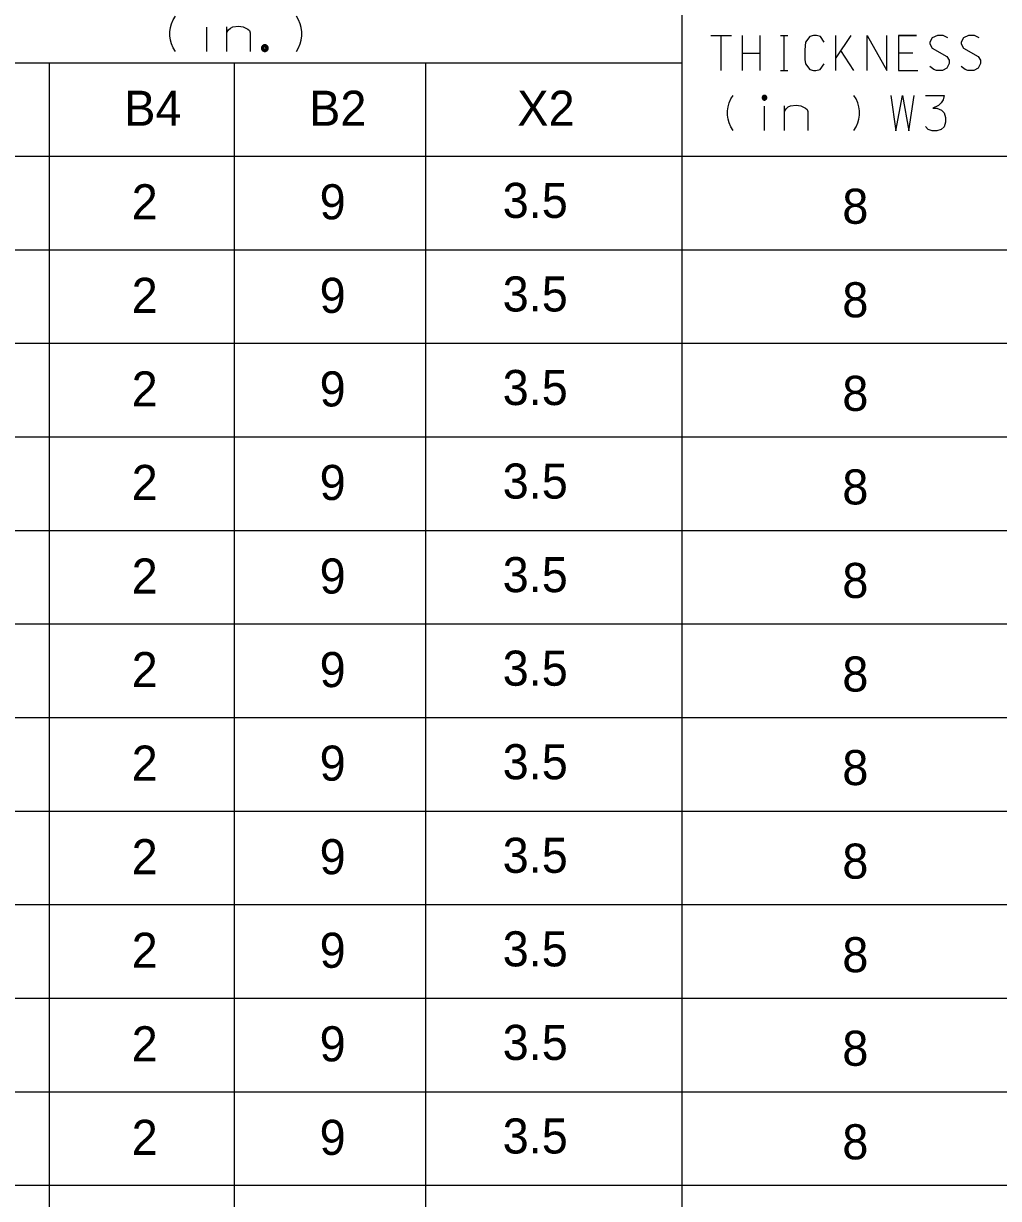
# Model space of a CAD drawing. Extents: x 635698 to 639877, y 296617 to 300175.
# Drawn here: x 639114.2 to 639197.6, y 298708.2 to 298808.7 of the extents above; entities that cross this region are included whole.
import ezdxf

# ---------------------------------------------------------------- set-up
doc = ezdxf.new("R2010")
doc.units = 0
for name, color, linetype in [('1', 7, 'Continuous'), ('2', 7, 'Continuous'), ('3', 7, 'Continuous')]:
    doc.layers.add(name, color=color, linetype=linetype)

msp = doc.modelspace()

# ---------------------------------------------------------------- linework, layer by layer
at = {"layer": '1'}
for points in [[(639173.01, 298807.65), (639174.79, 298807.65)], [(639173.9, 298804.65), (639173.9, 298807.65)], [(639173.9, 298804.65), (639173.9, 298807.65)], [(639175.68, 298807.65), (639175.68, 298804.65)], [(639177.21, 298807.65), (639177.21, 298804.65)], [(639178.96, 298807.65), (639179.59, 298807.65)], [(639179.28, 298804.65), (639179.28, 298807.65)], [(639182.72, 298807.06), (639182.38, 298807.55), (639182.04, 298807.65), (639181.8, 298807.65), (639181.49, 298807.55), (639181.12, 298807.06), (639181.04, 298806.4), (639181.04, 298806.04), (639181.04, 298805.81), (639181.06, 298805.59), (639181.12, 298805.22), (639181.49, 298804.74), (639181.8, 298804.65), (639182, 298804.65), (639182.36, 298804.74), (639182.72, 298805.22)], [(639183.72, 298804.65), (639183.72, 298807.65)], [(639184.99, 298807.65), (639183.72, 298805.74)], [(639186.4, 298804.65), (639186.4, 298807.65), (639188.07, 298804.65), (639188.07, 298807.65)], [(639190.62, 298807.65), (639189.07, 298807.65), (639189.07, 298804.65), (639190.73, 298804.65)], [(639189.07, 298807.65), (639190.62, 298807.65)], [(639193.3, 298807.44), (639192.88, 298807.65), (639192.39, 298807.65), (639191.94, 298807.44), (639191.75, 298807.06), (639191.75, 298806.92), (639191.96, 298806.56), (639193.2, 298805.85), (639193.41, 298805.52), (639193.39, 298805.24), (639193.2, 298804.86), (639192.83, 298804.65), (639192.32, 298804.65), (639192.09, 298804.74), (639191.75, 298805)], [(639195.98, 298807.44), (639195.56, 298807.65), (639195.07, 298807.65), (639194.62, 298807.44), (639194.43, 298807.06), (639194.43, 298806.92), (639194.64, 298806.56), (639195.87, 298805.85), (639196.09, 298805.52), (639196.07, 298805.24), (639195.87, 298804.86), (639195.51, 298804.65), (639195, 298804.65), (639194.77, 298804.74), (639194.43, 298805)], [(639185.25, 298804.65), (639184.14, 298806.35)], [(639175.68, 298806.14), (639177.21, 298806.14)], [(639189.07, 298806.16), (639190.29, 298806.16)], [(639189.07, 298806.16), (639190.29, 298806.16)], [(639178.96, 298804.65), (639179.59, 298804.65)]]:
    msp.add_lwpolyline(points, dxfattribs=at)
at = {"layer": '2'}
for p, q in [((639170.53, 298814.79), (639170.53, 298581.29)), ((639100.52, 298805.29), (639170.53, 298805.29)), ((639116.4, 298805.29), (639116.4, 298581.29)), ((639132.22, 298805.29), (639132.22, 298581.29)), ((639148.59, 298805.29), (639148.59, 298581.29)), ((639405.11, 298797.29), (638853.27, 298797.29)), ((639405.11, 298789.29), (638853.27, 298789.29)), ((639405.11, 298781.29), (638853.27, 298781.29)), ((639405.11, 298773.29), (638853.27, 298773.29)), ((639405.11, 298765.29), (638853.27, 298765.29)), ((639405.11, 298757.29), (638853.27, 298757.29)), ((639405.11, 298749.29), (638853.27, 298749.29)), ((639405.11, 298741.29), (638853.27, 298741.29)), ((639405.11, 298733.29), (638853.27, 298733.29)), ((639405.11, 298725.29), (638853.27, 298725.29)), ((639405.11, 298725.29), (638853.27, 298725.29)), ((639405.11, 298717.29), (638853.27, 298717.29)), ((639405.11, 298709.29), (638853.27, 298709.29))]:
    msp.add_line(p, q, dxfattribs=at)
at = {"layer": '3'}
for points in [[(639127.21, 298806.28), (639127.02, 298806.58), (639126.87, 298806.92), (639126.78, 298807.25), (639126.73, 298807.6), (639126.73, 298807.95), (639126.78, 298808.31), (639126.87, 298808.64), (639127.02, 298808.97), (639127.21, 298809.28)], [(639129.89, 298806.28), (639129.89, 298808.36)], [(639131.59, 298807.91), (639131.75, 298808.12), (639131.92, 298808.28), (639132.13, 298808.38), (639132.61, 298808.45), (639133.01, 298808.38), (639133.41, 298808.19), (639133.53, 298808.07), (639133.6, 298807.88), (639133.6, 298806.28)], [(639131.59, 298806.28), (639131.59, 298808.38)], [(639137.55, 298806.28), (639137.74, 298806.58), (639137.88, 298806.92), (639137.97, 298807.25), (639138.02, 298807.6), (639138.02, 298807.95), (639137.97, 298808.31), (639137.88, 298808.64), (639137.74, 298808.97), (639137.55, 298809.28)], [(639135.14, 298806.56), (639135.14, 298806.59), (639135.13, 298806.62), (639135.13, 298806.65), (639135.11, 298806.68), (639135.1, 298806.7), (639135.08, 298806.73), (639135.07, 298806.75), (639135.04, 298806.77), (639135.02, 298806.79), (639135, 298806.81), (639134.97, 298806.82), (639134.94, 298806.83), (639134.91, 298806.84), (639134.88, 298806.85), (639134.85, 298806.85), (639134.82, 298806.85), (639134.79, 298806.84), (639134.77, 298806.83), (639134.74, 298806.82), (639134.71, 298806.81), (639134.69, 298806.79), (639134.66, 298806.77), (639134.64, 298806.75), (639134.62, 298806.73), (639134.61, 298806.7), (639134.59, 298806.68), (639134.58, 298806.65), (639134.58, 298806.62), (639134.57, 298806.59), (639134.57, 298806.56), (639134.57, 298806.53), (639134.58, 298806.5), (639134.58, 298806.47), (639134.59, 298806.45), (639134.61, 298806.42), (639134.62, 298806.39), (639134.64, 298806.37), (639134.66, 298806.35), (639134.69, 298806.33), (639134.71, 298806.32), (639134.74, 298806.3), (639134.77, 298806.29), (639134.79, 298806.28), (639134.82, 298806.28), (639134.85, 298806.28), (639134.88, 298806.28), (639134.91, 298806.28), (639134.94, 298806.29), (639134.97, 298806.3), (639135, 298806.32), (639135.02, 298806.33), (639135.04, 298806.35), (639135.07, 298806.37), (639135.08, 298806.39), (639135.1, 298806.42), (639135.11, 298806.45), (639135.13, 298806.47), (639135.13, 298806.5), (639135.14, 298806.53), (639135.14, 298806.56)], [(639135.08, 298806.56), (639135.08, 298806.59), (639135.07, 298806.61), (639135.07, 298806.63), (639135.06, 298806.65), (639135.05, 298806.67), (639135.04, 298806.69), (639135.02, 298806.71), (639135, 298806.73), (639134.99, 298806.74), (639134.97, 298806.76), (639134.95, 298806.77), (639134.92, 298806.78), (639134.9, 298806.78), (639134.88, 298806.79), (639134.85, 298806.79), (639134.83, 298806.79), (639134.81, 298806.78), (639134.78, 298806.78), (639134.76, 298806.77), (639134.74, 298806.76), (639134.72, 298806.74), (639134.7, 298806.73), (639134.69, 298806.71), (639134.67, 298806.69), (639134.66, 298806.67), (639134.65, 298806.65), (639134.64, 298806.63), (639134.63, 298806.61), (639134.63, 298806.59), (639134.63, 298806.56), (639134.63, 298806.54), (639134.63, 298806.52), (639134.64, 298806.49), (639134.65, 298806.47), (639134.66, 298806.45), (639134.67, 298806.43), (639134.69, 298806.41), (639134.7, 298806.39), (639134.72, 298806.38), (639134.74, 298806.37), (639134.76, 298806.36), (639134.78, 298806.35), (639134.81, 298806.34), (639134.83, 298806.34), (639134.85, 298806.34), (639134.88, 298806.34), (639134.9, 298806.34), (639134.92, 298806.35), (639134.95, 298806.36), (639134.97, 298806.37), (639134.99, 298806.38), (639135, 298806.39), (639135.02, 298806.41), (639135.04, 298806.43), (639135.05, 298806.45), (639135.06, 298806.47), (639135.07, 298806.49), (639135.07, 298806.52), (639135.08, 298806.54), (639135.08, 298806.56)], [(639135.02, 298806.56), (639135.02, 298806.58), (639135.02, 298806.6), (639135.01, 298806.61), (639135, 298806.63), (639135, 298806.64), (639134.99, 298806.66), (639134.98, 298806.67), (639134.96, 298806.68), (639134.95, 298806.7), (639134.94, 298806.7), (639134.92, 298806.71), (639134.9, 298806.72), (639134.89, 298806.72), (639134.87, 298806.73), (639134.85, 298806.73), (639134.84, 298806.73), (639134.82, 298806.72), (639134.8, 298806.72), (639134.79, 298806.71), (639134.77, 298806.7), (639134.76, 298806.7), (639134.74, 298806.68), (639134.73, 298806.67), (639134.72, 298806.66), (639134.71, 298806.64), (639134.7, 298806.63), (639134.7, 298806.61), (639134.69, 298806.6), (639134.69, 298806.58), (639134.69, 298806.56), (639134.69, 298806.54), (639134.69, 298806.53), (639134.7, 298806.51), (639134.7, 298806.49), (639134.71, 298806.48), (639134.72, 298806.46), (639134.73, 298806.45), (639134.74, 298806.44), (639134.76, 298806.43), (639134.77, 298806.42), (639134.79, 298806.41), (639134.8, 298806.4), (639134.82, 298806.4), (639134.84, 298806.4), (639134.85, 298806.4), (639134.87, 298806.4), (639134.89, 298806.4), (639134.9, 298806.4), (639134.92, 298806.41), (639134.94, 298806.42), (639134.95, 298806.43), (639134.96, 298806.44), (639134.98, 298806.45), (639134.99, 298806.46), (639135, 298806.48), (639135, 298806.49), (639135.01, 298806.51), (639135.02, 298806.53), (639135.02, 298806.54), (639135.02, 298806.56)], [(639134.96, 298806.56), (639134.96, 298806.57), (639134.96, 298806.58), (639134.95, 298806.59), (639134.95, 298806.6), (639134.94, 298806.61), (639134.94, 298806.62), (639134.93, 298806.63), (639134.92, 298806.64), (639134.92, 298806.65), (639134.91, 298806.65), (639134.9, 298806.66), (639134.89, 298806.66), (639134.88, 298806.66), (639134.87, 298806.67), (639134.85, 298806.67), (639134.84, 298806.67), (639134.83, 298806.66), (639134.82, 298806.66), (639134.81, 298806.66), (639134.8, 298806.65), (639134.79, 298806.65), (639134.78, 298806.64), (639134.78, 298806.63), (639134.77, 298806.62), (639134.76, 298806.61), (639134.76, 298806.6), (639134.75, 298806.59), (639134.75, 298806.58), (639134.75, 298806.57), (639134.75, 298806.56), (639134.75, 298806.55), (639134.75, 298806.54), (639134.75, 298806.53), (639134.76, 298806.52), (639134.76, 298806.51), (639134.77, 298806.5), (639134.78, 298806.49), (639134.78, 298806.48), (639134.79, 298806.48), (639134.8, 298806.47), (639134.81, 298806.47), (639134.82, 298806.46), (639134.83, 298806.46), (639134.84, 298806.46), (639134.85, 298806.46), (639134.87, 298806.46), (639134.88, 298806.46), (639134.89, 298806.46), (639134.9, 298806.47), (639134.91, 298806.47), (639134.92, 298806.48), (639134.92, 298806.48), (639134.93, 298806.49), (639134.94, 298806.5), (639134.94, 298806.51), (639134.95, 298806.52), (639134.95, 298806.53), (639134.96, 298806.54), (639134.96, 298806.55), (639134.96, 298806.56)], [(639174.92, 298799.52), (639174.73, 298799.83), (639174.59, 298800.16), (639174.5, 298800.49), (639174.45, 298800.84), (639174.45, 298801.2), (639174.5, 298801.55), (639174.59, 298801.88), (639174.73, 298802.21), (639174.92, 298802.52)], [(639177.8, 298802.32), (639177.8, 298802.34), (639177.79, 298802.36), (639177.79, 298802.38), (639177.78, 298802.4), (639177.77, 298802.42), (639177.76, 298802.44), (639177.75, 298802.45), (639177.73, 298802.47), (639177.72, 298802.48), (639177.7, 298802.49), (639177.68, 298802.5), (639177.66, 298802.51), (639177.64, 298802.51), (639177.62, 298802.52), (639177.6, 298802.52), (639177.58, 298802.52), (639177.56, 298802.51), (639177.54, 298802.51), (639177.52, 298802.5), (639177.5, 298802.49), (639177.48, 298802.48), (639177.47, 298802.47), (639177.45, 298802.45), (639177.44, 298802.44), (639177.43, 298802.42), (639177.42, 298802.4), (639177.41, 298802.38), (639177.41, 298802.36), (639177.4, 298802.34), (639177.4, 298802.32), (639177.4, 298802.3), (639177.41, 298802.28), (639177.41, 298802.26), (639177.42, 298802.24), (639177.43, 298802.22), (639177.44, 298802.2), (639177.45, 298802.19), (639177.47, 298802.17), (639177.48, 298802.16), (639177.5, 298802.15), (639177.52, 298802.14), (639177.54, 298802.13), (639177.56, 298802.13), (639177.58, 298802.12), (639177.6, 298802.12), (639177.62, 298802.12), (639177.64, 298802.13), (639177.66, 298802.13), (639177.68, 298802.14), (639177.7, 298802.15), (639177.72, 298802.16), (639177.73, 298802.17), (639177.75, 298802.19), (639177.76, 298802.2), (639177.77, 298802.22), (639177.78, 298802.24), (639177.79, 298802.26), (639177.79, 298802.28), (639177.8, 298802.3), (639177.8, 298802.32)], [(639177.74, 298802.32), (639177.74, 298802.34), (639177.74, 298802.35), (639177.73, 298802.36), (639177.73, 298802.38), (639177.72, 298802.39), (639177.71, 298802.4), (639177.7, 298802.41), (639177.69, 298802.42), (639177.68, 298802.43), (639177.67, 298802.44), (639177.66, 298802.45), (639177.64, 298802.45), (639177.63, 298802.46), (639177.62, 298802.46), (639177.6, 298802.46), (639177.59, 298802.46), (639177.57, 298802.46), (639177.56, 298802.45), (639177.54, 298802.45), (639177.53, 298802.44), (639177.52, 298802.43), (639177.51, 298802.42), (639177.5, 298802.41), (639177.49, 298802.4), (639177.48, 298802.39), (639177.47, 298802.38), (639177.47, 298802.36), (639177.47, 298802.35), (639177.46, 298802.34), (639177.46, 298802.32), (639177.46, 298802.31), (639177.47, 298802.29), (639177.47, 298802.28), (639177.47, 298802.26), (639177.48, 298802.25), (639177.49, 298802.24), (639177.5, 298802.23), (639177.51, 298802.22), (639177.52, 298802.21), (639177.53, 298802.2), (639177.54, 298802.2), (639177.56, 298802.19), (639177.57, 298802.19), (639177.59, 298802.18), (639177.6, 298802.18), (639177.62, 298802.18), (639177.63, 298802.19), (639177.64, 298802.19), (639177.66, 298802.2), (639177.67, 298802.2), (639177.68, 298802.21), (639177.69, 298802.22), (639177.7, 298802.23), (639177.71, 298802.24), (639177.72, 298802.25), (639177.73, 298802.26), (639177.73, 298802.28), (639177.74, 298802.29), (639177.74, 298802.31), (639177.74, 298802.32)], [(639177.68, 298802.32), (639177.68, 298802.33), (639177.68, 298802.34), (639177.67, 298802.35), (639177.67, 298802.35), (639177.67, 298802.36), (639177.66, 298802.37), (639177.66, 298802.37), (639177.65, 298802.38), (639177.65, 298802.38), (639177.64, 298802.39), (639177.63, 298802.39), (639177.63, 298802.39), (639177.62, 298802.4), (639177.61, 298802.4), (639177.6, 298802.4), (639177.59, 298802.4), (639177.58, 298802.4), (639177.58, 298802.39), (639177.57, 298802.39), (639177.56, 298802.39), (639177.56, 298802.38), (639177.55, 298802.38), (639177.54, 298802.37), (639177.54, 298802.37), (639177.53, 298802.36), (639177.53, 298802.35), (639177.53, 298802.35), (639177.52, 298802.34), (639177.52, 298802.33), (639177.52, 298802.32), (639177.52, 298802.31), (639177.52, 298802.3), (639177.53, 298802.3), (639177.53, 298802.29), (639177.53, 298802.28), (639177.54, 298802.28), (639177.54, 298802.27), (639177.55, 298802.26), (639177.56, 298802.26), (639177.56, 298802.25), (639177.57, 298802.25), (639177.58, 298802.25), (639177.58, 298802.24), (639177.59, 298802.24), (639177.6, 298802.24), (639177.61, 298802.24), (639177.62, 298802.24), (639177.63, 298802.25), (639177.63, 298802.25), (639177.64, 298802.25), (639177.65, 298802.26), (639177.65, 298802.26), (639177.66, 298802.27), (639177.66, 298802.28), (639177.67, 298802.28), (639177.67, 298802.29), (639177.67, 298802.3), (639177.68, 298802.3), (639177.68, 298802.31), (639177.68, 298802.32)], [(639177.62, 298802.32), (639177.62, 298802.32), (639177.62, 298802.32), (639177.62, 298802.33), (639177.62, 298802.33), (639177.62, 298802.33), (639177.62, 298802.33), (639177.61, 298802.33), (639177.61, 298802.33), (639177.61, 298802.34), (639177.61, 298802.34), (639177.61, 298802.34), (639177.61, 298802.34), (639177.6, 298802.34), (639177.6, 298802.34), (639177.6, 298802.34), (639177.6, 298802.34), (639177.6, 298802.34), (639177.6, 298802.34), (639177.59, 298802.34), (639177.59, 298802.34), (639177.59, 298802.34), (639177.59, 298802.33), (639177.59, 298802.33), (639177.59, 298802.33), (639177.59, 298802.33), (639177.58, 298802.33), (639177.58, 298802.33), (639177.58, 298802.32), (639177.58, 298802.32), (639177.58, 298802.32), (639177.58, 298802.32), (639177.58, 298802.32), (639177.58, 298802.32), (639177.58, 298802.31), (639177.59, 298802.31), (639177.59, 298802.31), (639177.59, 298802.31), (639177.59, 298802.31), (639177.59, 298802.31), (639177.59, 298802.31), (639177.59, 298802.3), (639177.6, 298802.3), (639177.6, 298802.3), (639177.6, 298802.3), (639177.6, 298802.3), (639177.6, 298802.3), (639177.6, 298802.3), (639177.61, 298802.3), (639177.61, 298802.3), (639177.61, 298802.31), (639177.61, 298802.31), (639177.61, 298802.31), (639177.61, 298802.31), (639177.62, 298802.31), (639177.62, 298802.31), (639177.62, 298802.31), (639177.62, 298802.32), (639177.62, 298802.32), (639177.62, 298802.32), (639177.62, 298802.32)], [(639185.25, 298799.52), (639185.44, 298799.83), (639185.58, 298800.16), (639185.68, 298800.49), (639185.73, 298800.84), (639185.73, 298801.2), (639185.68, 298801.55), (639185.58, 298801.88), (639185.44, 298802.21), (639185.25, 298802.52)], [(639188.42, 298802.5), (639188.84, 298799.5), (639189.41, 298802.5), (639189.95, 298799.5), (639190.42, 298802.5)], [(639191.39, 298802.5), (639192.98, 298802.5), (639192.88, 298802.15), (639192.72, 298801.89), (639192.48, 298801.65), (639192.01, 298801.42), (639192.36, 298801.42), (639192.74, 298801.25), (639192.98, 298801.02), (639193.09, 298800.64), (639193.09, 298800.24), (639192.98, 298799.84), (639192.72, 298799.6), (639192.36, 298799.5), (639191.96, 298799.5), (639191.61, 298799.6), (639191.39, 298799.86)], [(639177.6, 298799.52), (639177.6, 298801.6)], [(639179.3, 298801.15), (639179.47, 298801.36), (639179.63, 298801.53), (639179.84, 298801.62), (639180.32, 298801.69), (639180.72, 298801.62), (639181.12, 298801.43), (639181.24, 298801.31), (639181.31, 298801.13), (639181.31, 298799.52)], [(639179.3, 298799.52), (639179.3, 298801.62)]]:
    msp.add_lwpolyline(points, dxfattribs=at)

# ---------------------------------------------------------------- texts
at = {"layer": '2'}
for s, p in [('B4', (639122.82, 298799.92)), ('B2', (639138.64, 298799.92)), ('X2', (639156.45, 298799.92)), ('2', (639123.46, 298791.92)), ('9', (639139.54, 298791.92)), ('3.5', (639155.2, 298792.04)), ('8', (639184.26, 298791.54)), ('2', (639123.46, 298783.92)), ('9', (639139.54, 298783.92)), ('3.5', (639155.2, 298784.04)), ('8', (639184.26, 298783.54)), ('2', (639123.46, 298775.92)), ('9', (639139.54, 298775.92)), ('3.5', (639155.2, 298776.04)), ('8', (639184.26, 298775.54)), ('2', (639123.46, 298767.92)), ('9', (639139.54, 298767.92)), ('3.5', (639155.2, 298768.04)), ('8', (639184.26, 298767.54)), ('2', (639123.46, 298759.92)), ('9', (639139.54, 298759.92)), ('3.5', (639155.2, 298760.04)), ('8', (639184.26, 298759.54)), ('3.5', (639155.2, 298752.04)), ('2', (639123.46, 298751.92)), ('9', (639139.54, 298751.92)), ('8', (639184.26, 298751.54)), ('3.5', (639155.2, 298744.04)), ('2', (639123.46, 298743.92)), ('9', (639139.54, 298743.92)), ('8', (639184.26, 298743.54)), ('3.5', (639155.2, 298736.04)), ('2', (639123.46, 298735.92)), ('9', (639139.54, 298735.92)), ('8', (639184.26, 298735.54)), ('2', (639123.46, 298727.92)), ('9', (639139.54, 298727.92)), ('3.5', (639155.2, 298728.04)), ('8', (639184.26, 298727.54)), ('2', (639123.46, 298719.92)), ('9', (639139.54, 298719.92)), ('3.5', (639155.2, 298720.04)), ('8', (639184.26, 298719.54)), ('2', (639123.46, 298711.92)), ('9', (639139.54, 298711.92)), ('3.5', (639155.2, 298712.04)), ('8', (639184.26, 298711.54))]:
    msp.add_text(s, height=3, dxfattribs=at).set_placement(p)

doc.saveas('drawing.dxf')
